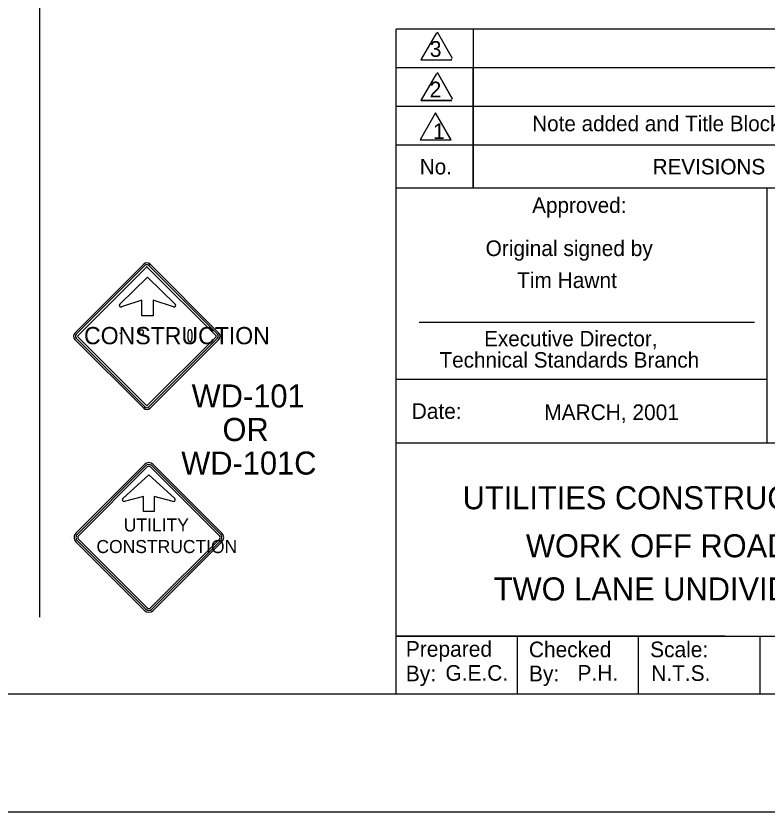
# Model space of a CAD drawing. Extents: x 1342 to 1558, y 178 to 457.
# Drawn here: x 1449.5 to 1518.5, y 177.9 to 251 of the extents above; entities that cross this region are included whole.
import ezdxf

# ---------------------------------------------------------------- set-up
doc = ezdxf.new("R2010")
doc.units = 0
for name, color, linetype in [('Level 1', 7, 'Continuous'), ('Level 10', 7, 'Continuous'), ('Level 60', 7, 'Continuous')]:
    doc.layers.add(name, color=color, linetype=linetype)

msp = doc.modelspace()

# ---------------------------------------------------------------- linework, layer by layer
at = {"layer": 'Level 1'}
for p, q in [((1454.953, 221.873), (1461.263, 228.183)), ((1455.068, 221.758), (1461.378, 228.068)), ((1455.206, 221.62), (1461.516, 227.93)), ((1461.594, 227.93), (1467.905, 221.62)), ((1461.847, 228.183), (1461.732, 228.068)), ((1461.732, 228.068), (1468.042, 221.758)), ((1461.732, 228.068), (1461.732, 228.068)), ((1461.847, 228.183), (1468.157, 221.873)), ((1459.07, 224.537), (1461.611, 227.012)), ((1461.612, 227.012), (1464.153, 224.537)), ((1461.085, 224.907), (1459.236, 224.268)), ((1461.085, 223.45), (1461.085, 224.907)), ((1463.987, 224.268), (1462.138, 224.907)), ((1462.138, 224.907), (1462.138, 223.45)), ((1462.138, 223.45), (1461.085, 223.45)), ((1461.114, 222.145), (1461.125, 222.145)), ((1461.114, 222.145), (1461.125, 222.145)), ((1461.378, 215.094), (1455.068, 221.404)), ((1461.516, 215.232), (1455.206, 221.542)), ((1467.905, 221.542), (1461.594, 215.232)), ((1468.042, 221.404), (1461.732, 215.094)), ((1461.263, 214.979), (1454.953, 221.289)), ((1468.157, 221.289), (1461.847, 214.979)), ((1461.378, 215.094), (1461.263, 214.979)), ((1461.263, 214.98), (1461.263, 214.979)), ((1461.378, 215.095), (1461.378, 215.094)), ((1461.531, 215.247), (1461.516, 215.232)), ((1459.47, 206.433), (1459.47, 206.433)), ((1459.47, 206.433), (1459.47, 206.433)), ((1459.47, 206.433), (1459.47, 206.433)), ((1454.646, 203.124), (1454.646, 203.124))]:
    msp.add_line(p, q, dxfattribs=at)
for points in [[(1461.125, 222.145), (1460.878, 222.145), (1460.878, 221.785), (1461.125, 221.785)], [(1461.125, 222.145), (1460.878, 222.145), (1460.878, 221.785), (1461.125, 221.785)], [(1461.114, 221.785), (1461.125, 221.785), (1461.137, 221.796), (1461.148, 221.796), (1461.159, 221.796), (1461.171, 221.796), (1461.171, 221.807), (1461.182, 221.807), (1461.193, 221.807), (1461.204, 221.819), (1461.216, 221.83), (1461.227, 221.841), (1461.238, 221.852), (1461.238, 221.864), (1461.238, 221.875), (1461.249, 221.897), (1461.249, 221.909), (1461.249, 221.92), (1461.249, 221.942), (1461.261, 221.954), (1461.261, 221.965), (1461.261, 221.987), (1461.249, 221.999), (1461.249, 222.01), (1461.249, 222.032), (1461.249, 222.044), (1461.238, 222.055), (1461.238, 222.078), (1461.227, 222.089), (1461.227, 222.1), (1461.216, 222.111), (1461.204, 222.111), (1461.204, 222.123), (1461.193, 222.123), (1461.182, 222.134), (1461.171, 222.134), (1461.159, 222.134), (1461.148, 222.145), (1461.137, 222.145), (1461.125, 222.145), (1461.114, 222.145)], [(1461.114, 221.785), (1461.125, 221.785), (1461.137, 221.796), (1461.148, 221.796), (1461.159, 221.796), (1461.171, 221.796), (1461.171, 221.807), (1461.182, 221.807), (1461.193, 221.807), (1461.204, 221.819), (1461.216, 221.83), (1461.227, 221.841), (1461.238, 221.852), (1461.238, 221.864), (1461.238, 221.875), (1461.249, 221.897), (1461.249, 221.909), (1461.249, 221.92), (1461.249, 221.942), (1461.261, 221.954), (1461.261, 221.965), (1461.261, 221.987), (1461.249, 221.999), (1461.249, 222.01), (1461.249, 222.032), (1461.249, 222.044), (1461.238, 222.055), (1461.238, 222.078), (1461.227, 222.089), (1461.227, 222.1), (1461.216, 222.111), (1461.204, 222.111), (1461.204, 222.123), (1461.193, 222.123), (1461.182, 222.134), (1461.171, 222.134), (1461.159, 222.134), (1461.148, 222.145), (1461.137, 222.145), (1461.125, 222.145), (1461.114, 222.145)], [(1465.36, 221.199), (1465.371, 221.188), (1465.371, 221.177), (1465.382, 221.165), (1465.394, 221.154), (1465.394, 221.143), (1465.405, 221.132), (1465.416, 221.132), (1465.427, 221.12), (1465.439, 221.12), (1465.439, 221.109), (1465.45, 221.109), (1465.461, 221.109), (1465.473, 221.098), (1465.484, 221.098), (1465.495, 221.098), (1465.506, 221.098), (1465.518, 221.098), (1465.529, 221.098), (1465.54, 221.098), (1465.551, 221.098), (1465.563, 221.109), (1465.574, 221.109), (1465.585, 221.109), (1465.596, 221.12), (1465.608, 221.132), (1465.619, 221.143), (1465.63, 221.143), (1465.63, 221.154), (1465.641, 221.165), (1465.653, 221.177), (1465.664, 221.188), (1465.664, 221.199), (1465.675, 221.233), (1465.675, 221.267), (1465.686, 221.301), (1465.698, 221.334), (1465.698, 221.368), (1465.709, 221.402), (1465.709, 221.447), (1465.72, 221.481), (1465.72, 221.515), (1465.72, 221.548), (1465.72, 221.582), (1465.72, 221.616), (1465.72, 221.65), (1465.72, 221.683), (1465.72, 221.717), (1465.72, 221.751), (1465.709, 221.796), (1465.709, 221.83), (1465.709, 221.864), (1465.698, 221.897), (1465.698, 221.931), (1465.686, 221.965), (1465.675, 221.999), (1465.675, 222.032), (1465.664, 222.066), (1465.653, 222.078), (1465.653, 222.089), (1465.641, 222.1), (1465.63, 222.111), (1465.63, 222.123), (1465.619, 222.134), (1465.608, 222.134), (1465.596, 222.145), (1465.585, 222.156), (1465.574, 222.156), (1465.563, 222.156), (1465.551, 222.168), (1465.54, 222.168), (1465.529, 222.168), (1465.518, 222.168), (1465.506, 222.168), (1465.495, 222.168), (1465.484, 222.168), (1465.473, 222.168), (1465.461, 222.168), (1465.45, 222.156), (1465.439, 222.156), (1465.439, 222.145), (1465.427, 222.145), (1465.416, 222.134), (1465.405, 222.134), (1465.405, 222.123), (1465.394, 222.111), (1465.382, 222.111), (1465.382, 222.1), (1465.371, 222.089), (1465.371, 222.078), (1465.36, 222.066), (1465.36, 222.055), (1465.36, 222.044), (1465.36, 222.032), (1465.349, 221.999), (1465.337, 221.976), (1465.337, 221.942), (1465.326, 221.909), (1465.315, 221.875), (1465.315, 221.841), (1465.315, 221.807)], [(1465.36, 221.199), (1465.371, 221.188), (1465.371, 221.177), (1465.382, 221.165), (1465.394, 221.154), (1465.394, 221.143), (1465.405, 221.132), (1465.416, 221.132), (1465.427, 221.12), (1465.439, 221.12), (1465.439, 221.109), (1465.45, 221.109), (1465.461, 221.109), (1465.473, 221.098), (1465.484, 221.098), (1465.495, 221.098), (1465.506, 221.098), (1465.518, 221.098), (1465.529, 221.098), (1465.54, 221.098), (1465.551, 221.098), (1465.563, 221.109), (1465.574, 221.109), (1465.585, 221.109), (1465.596, 221.12), (1465.608, 221.132), (1465.619, 221.143), (1465.63, 221.143), (1465.63, 221.154), (1465.641, 221.165), (1465.653, 221.177), (1465.664, 221.188), (1465.664, 221.199), (1465.675, 221.233), (1465.675, 221.267), (1465.686, 221.301), (1465.698, 221.334), (1465.698, 221.368), (1465.709, 221.402), (1465.709, 221.447), (1465.72, 221.481), (1465.72, 221.515), (1465.72, 221.548), (1465.72, 221.582), (1465.72, 221.616), (1465.72, 221.65), (1465.72, 221.683), (1465.72, 221.717), (1465.72, 221.751), (1465.709, 221.796), (1465.709, 221.83), (1465.709, 221.864), (1465.698, 221.897), (1465.698, 221.931), (1465.686, 221.965), (1465.675, 221.999), (1465.675, 222.032), (1465.664, 222.066), (1465.653, 222.078), (1465.653, 222.089), (1465.641, 222.1), (1465.63, 222.111), (1465.63, 222.123), (1465.619, 222.134), (1465.608, 222.134), (1465.596, 222.145), (1465.585, 222.156), (1465.574, 222.156), (1465.563, 222.156), (1465.551, 222.168), (1465.54, 222.168), (1465.529, 222.168), (1465.518, 222.168), (1465.506, 222.168), (1465.495, 222.168), (1465.484, 222.168), (1465.473, 222.168), (1465.461, 222.168), (1465.45, 222.156), (1465.439, 222.156), (1465.439, 222.145), (1465.427, 222.145), (1465.416, 222.134), (1465.405, 222.134), (1465.405, 222.123), (1465.394, 222.111), (1465.382, 222.111), (1465.382, 222.1), (1465.371, 222.089), (1465.371, 222.078), (1465.36, 222.066), (1465.36, 222.055), (1465.36, 222.044), (1465.36, 222.032), (1465.349, 221.999), (1465.337, 221.976), (1465.337, 221.942), (1465.326, 221.909), (1465.315, 221.875), (1465.315, 221.841), (1465.315, 221.807)], [(1459.245, 221.785), (1459.087, 221.875)], [(1465.315, 221.807), (1465.304, 221.774), (1465.304, 221.74), (1465.304, 221.706), (1465.304, 221.672), (1465.304, 221.638), (1465.304, 221.605), (1465.304, 221.571), (1465.304, 221.537), (1465.304, 221.503), (1465.315, 221.469), (1465.315, 221.436), (1465.315, 221.402), (1465.326, 221.368), (1465.326, 221.334), (1465.337, 221.301), (1465.349, 221.267), (1465.349, 221.233), (1465.36, 221.199)], [(1465.315, 221.807), (1465.304, 221.774), (1465.304, 221.74), (1465.304, 221.706), (1465.304, 221.672), (1465.304, 221.638), (1465.304, 221.605), (1465.304, 221.571), (1465.304, 221.537), (1465.304, 221.503), (1465.315, 221.469), (1465.315, 221.436), (1465.315, 221.402), (1465.326, 221.368), (1465.326, 221.334), (1465.337, 221.301), (1465.349, 221.267), (1465.349, 221.233), (1465.36, 221.199)], [(1455.04, 203.519), (1461.351, 209.829)], [(1455.158, 203.401), (1461.469, 209.711)], [(1462.02, 209.711), (1468.332, 203.398)], [(1462.139, 209.828), (1468.451, 203.516)], [(1455.277, 203.282), (1461.588, 209.592)], [(1461.903, 209.592), (1468.214, 203.279)], [(1459.336, 206.688), (1461.724, 208.862), (1464.115, 206.688)], [(1459.336, 206.688), (1461.724, 208.862), (1464.115, 206.688)], [(1459.336, 206.688), (1461.724, 208.862), (1464.115, 206.688)], [(1463.977, 206.433), (1462.221, 206.885), (1462.221, 205.516), (1461.232, 205.516), (1461.232, 206.885), (1459.47, 206.433)], [(1463.977, 206.433), (1462.221, 206.885), (1462.221, 205.516), (1461.232, 205.516), (1461.232, 206.885), (1459.47, 206.433)], [(1463.977, 206.433), (1462.221, 206.885), (1462.221, 205.516), (1461.232, 205.516), (1461.232, 206.885), (1459.47, 206.433)], [(1461.351, 196.418), (1455.04, 202.729)], [(1461.469, 196.537), (1455.158, 202.848)], [(1461.588, 196.654), (1455.277, 202.966)], [(1468.214, 202.964), (1461.903, 196.654)], [(1468.332, 202.846), (1462.021, 196.537)], [(1468.451, 202.728), (1462.139, 196.418)]]:
    msp.add_lwpolyline(points, dxfattribs=at)
for centre, radius, start, end in [((1461.555, 227.892), 0.413, 45.00012, 135), ((1461.555, 227.892), 0.25, 45.00012, 135), ((1461.555, 227.892), 0.0552, 44.99999, 135), ((1459.183, 224.422), 0.162, 134.244, 289.06341), ((1464.04, 224.422), 0.162, 250.93659, 45.756), ((1455.245, 221.581), 0.413, 135, 225), ((1455.245, 221.581), 0.25, 135, 225.00066), ((1455.245, 221.581), 0.0552, 135, 225), ((1467.865, 221.581), 0.0552, 315.00001, 44.99827), ((1467.865, 221.581), 0.25, 315, 45), ((1467.865, 221.581), 0.413, 315, 45), ((1461.555, 215.271), 0.413, 225, 315), ((1461.555, 215.271), 0.25, 224.99953, 315.00034), ((1461.555, 215.271), 0.0553, 225, 315.00069), ((1461.745, 209.433), 0.558, 44.99496, 134.99496), ((1461.745, 209.433), 0.558, 44.99496, 134.99496), ((1461.745, 209.433), 0.39, 44.99496, 134.99496), ((1461.745, 209.433), 0.223, 44.99496, 134.99496), ((1459.437, 206.577), 0.15, 132.30479, 284.40748), ((1459.437, 206.577), 0.15, 132.30479, 284.40748), ((1459.437, 206.577), 0.15, 132.30479, 284.40748), ((1464.015, 206.577), 0.15, 255.59252, 47.69521), ((1464.015, 206.577), 0.15, 255.59252, 47.69521), ((1464.015, 206.577), 0.15, 255.59252, 47.69521), ((1455.435, 203.124), 0.558, 134.99495, 224.99495), ((1455.435, 203.124), 0.39, 134.99495, 224.99495), ((1455.435, 203.124), 0.223, 134.99495, 224.99495), ((1468.056, 203.121), 0.223, 314.99496, 44.99495), ((1468.056, 203.121), 0.39, 314.99496, 44.99495), ((1468.056, 203.121), 0.558, 314.99496, 44.99495), ((1461.746, 196.812), 0.39, 224.99496, 314.99495), ((1461.746, 196.812), 0.223, 224.99496, 314.99495), ((1461.746, 196.812), 0.558, 224.99496, 314.99495)]:
    msp.add_arc(centre, radius, start, end, dxfattribs=at)
at = {"layer": 'Level 10'}
msp.add_line((1451.693, 440.384), (1451.693, 195.81), dxfattribs=at)
at = {"layer": 'Level 60'}
for p, q in [((1548.312, 249.746), (1484.432, 249.746)), ((1484.439, 243.274), (1484.439, 249.746)), ((1491.529, 243.274), (1491.529, 249.746)), ((1548.312, 246.197), (1484.432, 246.197)), ((1484.439, 243.27), (1484.439, 246.191)), ((1491.526, 243.27), (1491.526, 246.191)), ((1484.439, 235.196), (1484.439, 243.274)), ((1484.439, 235.196), (1484.439, 243.27)), ((1491.526, 235.196), (1491.526, 243.27)), ((1491.529, 235.196), (1491.529, 243.274)), ((1548.312, 242.648), (1484.432, 242.648)), ((1548.312, 239.1), (1484.432, 239.1)), ((1484.439, 188.732), (1484.439, 235.196)), ((1484.439, 235.196), (1548.282, 235.196)), ((1484.439, 235.196), (1548.312, 235.196)), ((1518.489, 235.196), (1518.489, 211.787)), ((1518.489, 235.196), (1518.489, 235.196)), ((1486.547, 222.882), (1517.348, 222.882)), ((1484.439, 217.639), (1518.489, 217.639)), ((1484.439, 211.787), (1548.282, 211.787)), ((1484.439, 194.053), (1548.282, 194.053)), ((1514.639, 194.053), (1484.439, 194.053)), ((1495.57, 188.732), (1495.57, 194.053)), ((1506.7, 188.732), (1506.7, 194.053)), ((1517.829, 194.053), (1517.829, 188.732)), ((1499.902, 188.732), (1499.902, 188.732))]:
    msp.add_line(p, q, dxfattribs=at)
for points in [[(1342.282, 456.923), (1558.282, 456.923), (1558.282, 177.923), (1342.282, 177.923)], [(1361.408, 446.114), (1548.282, 446.114), (1548.282, 188.732), (1361.408, 188.732)], [(1488.057, 242.078), (1486.639, 239.609), (1489.476, 239.609)], [(1488.059, 242.081), (1486.64, 239.611), (1489.478, 239.611)]]:
    msp.add_lwpolyline(points, close=True, dxfattribs=at)
for points in [[(1488.138, 249.415), (1486.745, 246.99)], [(1489.62, 247.067), (1488.226, 249.492)], [(1486.745, 246.99), (1486.719, 246.945), (1489.558, 246.945), (1489.532, 246.99)], [(1488.136, 245.694), (1486.744, 243.27)], [(1488.138, 245.699), (1486.745, 243.274)], [(1489.618, 243.347), (1488.224, 245.771)], [(1489.62, 243.351), (1488.226, 245.776)], [(1486.744, 243.27), (1486.718, 243.225), (1489.556, 243.225), (1489.53, 243.27)], [(1486.745, 243.274), (1486.719, 243.229), (1489.558, 243.229), (1489.532, 243.274)]]:
    msp.add_lwpolyline(points, dxfattribs=at)

# ---------------------------------------------------------------- texts
at = {"layer": 'Level 1'}
for s, height, p in [('CONSTRUCTION', 1.584, (1455.785, 220.847)), ('UTILITY', 1.2, (1459.435, 203.667)), ('CONSTRUCTION', 1.2, (1456.926, 201.686))]:
    msp.add_text(s, height=height, dxfattribs=at).set_placement(p)
at = {"layer": 'Level 10'}
for s, p in [('WD-101', (1465.668, 215.048)), ('OR', (1468.499, 211.968)), ('WD-101C', (1464.709, 208.888))]:
    msp.add_text(s, height=2.1151, rotation=360, dxfattribs=at).set_placement(p)
at = {"layer": 'Level 60'}
for s, height, rotation, p in [('3', 1.448, 360, (1487.528, 247.214)), ('2', 1.447, 360, (1487.51, 243.494)), ('2', 1.448, 360, (1487.511, 243.498)), ('1', 1.447, 360, (1487.831, 239.666)), ('1', 1.448, 360, (1487.832, 239.668)), ('No.', 1.4188, 360, (1486.61, 236.43)), ('No.', 1.4195, 360, (1486.611, 236.431)), ('REVISIONS', 1.4188, 360, (1507.983, 236.43)), ('REVISIONS', 1.4195, 360, (1507.994, 236.431)), ('Date:', 1.4329, 360, (1485.873, 214.001)), ('UTILITIES CONSTRUCTION - SIGNING', 2.115, 359.99999, (1490.542, 205.707)), ('WORK OFF ROAD SURFACE', 2.115, 359.99999, (1496.353, 201.3)), ('TWO LANE UNDIVIDED HIGHWAY', 2.11517, 359.99999, (1493.403, 197.34)), ('Prepared', 1.44, 360, (1485.327, 192.173)), ('Checked', 1.4329, 360, (1496.633, 192.131)), ('Scale:', 1.4329, 360, (1507.763, 192.131)), ('G.E.C.', 1.433, 360, (1488.97, 189.974)), ('P.H.', 1.433, 360, (1501.092, 189.974)), ('    N.T.S.   ', 1.43292, 360, (1505.734, 189.96)), ('By:', 1.44, 360, (1485.327, 189.917)), ('By:', 1.44, 360, (1496.633, 189.917))]:
    msp.add_text(s, height=height, rotation=rotation, dxfattribs=at).set_placement(p)
for s, height, p in [('Note added and Title Block updated.', 1.419, (1496.933, 240.394)), ('Approved:', 1.4187, (1496.933, 232.902)), ('Original signed by', 1.434, (1492.654, 228.939)), ('Tim Hawnt', 1.434, (1495.544, 226.005)), ('Executive Director,', 1.41872, (1492.521, 220.654)), ('Technical Standards Branch', 1.41872, (1488.427, 218.703)), ('MARCH, 2001', 1.434, (1498.039, 213.89))]:
    msp.add_text(s, height=height, dxfattribs=at).set_placement(p)

doc.saveas('drawing.dxf')
